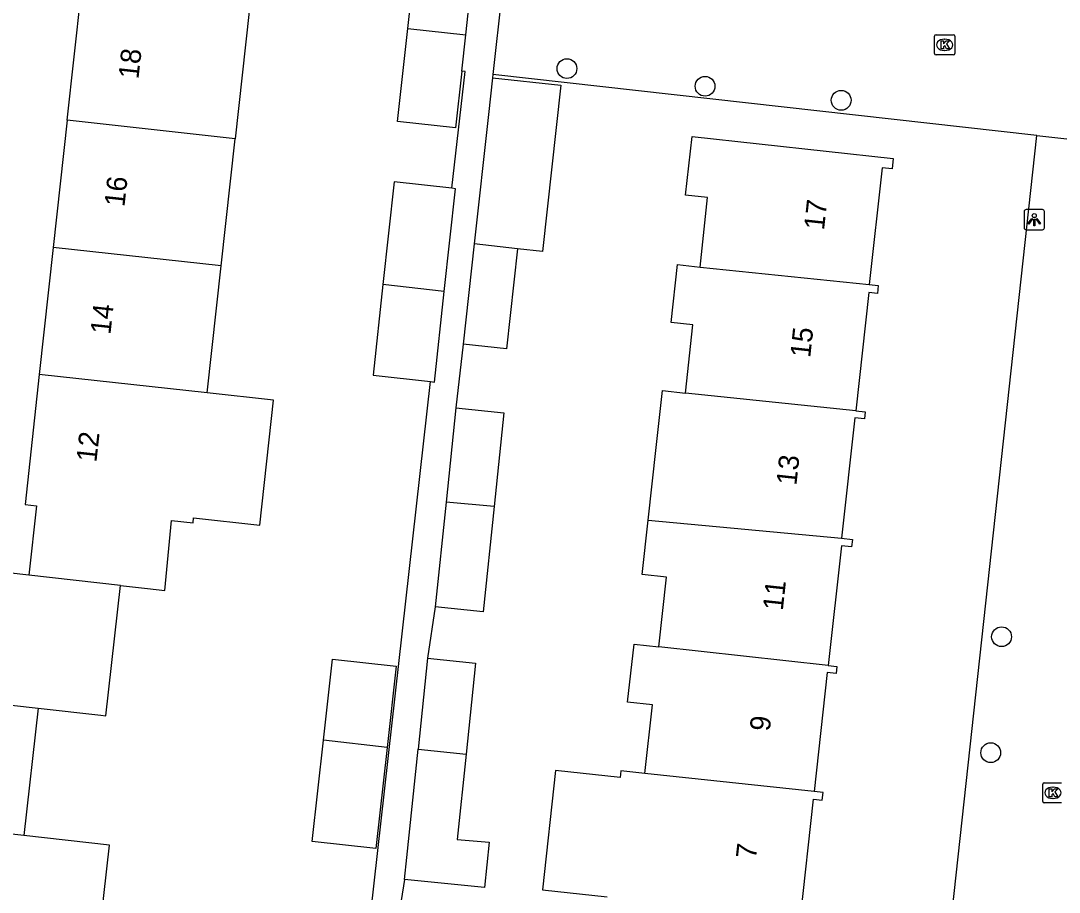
# Model space of a CAD drawing. Extents: x 162082 to 163393, y 388091 to 388632.
# Drawn here: x 162829.3 to 162880.7, y 388375.8 to 388418.8 of the extents above; entities that cross this region are included whole.
import ezdxf

# ---------------------------------------------------------------- set-up
doc = ezdxf.new("R2010")
doc.units = 0
for name, color, linetype in [('IMGEO_Boom', 7, 'Continuous'), ('IMGEO_Kolk', 7, 'Continuous'), ('IMGEO_Lichtpunt', 7, 'Continuous'), ('IMGEO_Pand', 7, 'Continuous'), ('IMGEO_Pand_nummerreeks', 7, 'Continuous'), ('IMGEO_Rijbaan_lokaal_open', 7, 'Continuous'), ('IMGEO_Voetpad_open', 7, 'Continuous')]:
    doc.layers.add(name, color=color, linetype=linetype)

msp = doc.modelspace()

# ---------------------------------------------------------------- linework, layer by layer
at = {"layer": 'IMGEO_Boom'}
for centre in [(162856.338, 388416.477), (162863.166, 388415.604), (162869.893, 388414.909), (162877.819, 388388.4), (162877.283, 388382.671)]:
    msp.add_circle(centre, 0.489, dxfattribs=at)
at = {"layer": 'IMGEO_Kolk'}
for p, q in [((162874.506, 388417.224), (162874.506, 388418.076)), ((162874.581, 388418.15), (162875.433, 388418.15)), ((162874.994, 388417.93), (162875.019, 388417.93)), ((162875.507, 388418.076), (162875.507, 388417.224)), ((162875.017, 388417.37), (162874.992, 388417.37)), ((162875.433, 388417.15), (162874.581, 388417.15)), ((162879.857, 388380.262), (162879.857, 388381.114)), ((162879.932, 388381.188), (162880.784, 388381.188)), ((162880.345, 388380.968), (162880.37, 388380.968)), ((162880.368, 388380.408), (162880.343, 388380.408)), ((162880.784, 388380.188), (162879.932, 388380.188))]:
    msp.add_line(p, q, dxfattribs=at)
for points in [[(162874.506, 388417.224), (162874.506, 388418.076)], [(162874.581, 388418.15), (162875.433, 388418.15)], [(162874.827, 388417.85), (162874.95, 388417.85), (162874.95, 388417.699), (162875.08, 388417.85), (162875.244, 388417.85), (162875.098, 388417.699), (162875.251, 388417.45), (162875.099, 388417.45), (162875.014, 388417.614), (162874.95, 388417.547), (162874.95, 388417.45), (162874.827, 388417.45), (162874.827, 388417.85)], [(162875.507, 388418.076), (162875.507, 388417.224)], [(162875.433, 388417.15), (162874.581, 388417.15)], [(162879.857, 388380.262), (162879.857, 388381.114)], [(162879.932, 388381.188), (162880.784, 388381.188)], [(162880.178, 388380.888), (162880.301, 388380.888), (162880.301, 388380.737), (162880.431, 388380.888), (162880.595, 388380.888), (162880.449, 388380.737), (162880.602, 388380.488), (162880.45, 388380.488), (162880.365, 388380.652), (162880.301, 388380.585), (162880.301, 388380.488), (162880.178, 388380.488), (162880.178, 388380.888)], [(162880.784, 388380.188), (162879.932, 388380.188)]]:
    msp.add_lwpolyline(points, dxfattribs=at)
for centre, start, end in [((162874.583, 388418.074), 91.552, 178.448), ((162874.583, 388418.074), 91.552, 178.448), ((162875.431, 388418.074), 1.552, 88.448), ((162875.431, 388418.074), 1.552, 88.448), ((162874.583, 388417.226), 181.552, 268.448), ((162874.583, 388417.226), 181.552, 268.448), ((162875.431, 388417.226), 271.552, 358.448), ((162875.431, 388417.226), 271.552, 358.448), ((162879.934, 388381.112), 91.552, 178.448), ((162879.934, 388381.112), 91.552, 178.448), ((162879.934, 388380.264), 181.552, 268.448), ((162879.934, 388380.264), 181.552, 268.448)]:
    msp.add_arc(centre, 0.0765, start, end, dxfattribs=at)
for centre, major_axis, ratio, start_param, end_param in [((162874.993, 388417.65), (-0.387, 0.002), 0.722429, 4.712389, 7.853982), ((162875.018, 388417.65), (-0.39, 0.002), 0.717154, 1.570796, 4.712389), ((162880.344, 388380.688), (-0.387, 0.002), 0.722429, 4.712389, 7.853982), ((162880.369, 388380.688), (-0.39, 0.002), 0.717154, 1.570796, 4.712389)]:
    msp.add_ellipse(centre, major_axis=major_axis, ratio=ratio, start_param=start_param, end_param=end_param, dxfattribs=at)
at = {"layer": 'IMGEO_Lichtpunt'}
for p, q in [((162878.937, 388409.413), (162878.937, 388408.606)), ((162878.937, 388409.413), (162878.937, 388408.606)), ((162879.839, 388409.508), (162879.031, 388409.508)), ((162879.839, 388409.508), (162879.031, 388409.508)), ((162879.933, 388408.606), (162879.933, 388409.413)), ((162879.933, 388408.606), (162879.933, 388409.413)), ((162879.031, 388408.512), (162879.839, 388408.512)), ((162879.031, 388408.512), (162879.839, 388408.512))]:
    msp.add_line(p, q, dxfattribs=at)
for points in [[(162879.311, 388409.077), (162879.35, 388409.049), (162879.162, 388408.787), (162879.124, 388408.814), (162879.311, 388409.077)], [(162879.523, 388409.049), (162879.561, 388409.076), (162879.748, 388408.814), (162879.709, 388408.786), (162879.523, 388409.049)], [(162879.413, 388409.029), (162879.46, 388409.029), (162879.46, 388408.707), (162879.413, 388408.707), (162879.413, 388409.029)]]:
    msp.add_lwpolyline(points, dxfattribs=at)
msp.add_circle((162879.436, 388409.211), 0.0994, dxfattribs=at)
for centre, start, end in [((162879.031, 388409.413), 90, 180), ((162879.031, 388409.413), 90, 180), ((162879.839, 388409.413), 0, 90), ((162879.839, 388409.413), 0, 90), ((162879.031, 388408.606), 180, 270), ((162879.031, 388408.606), 180, 270), ((162879.839, 388408.606), 270, 0), ((162879.839, 388408.606), 270, 360)]:
    msp.add_arc(centre, 0.0946, start, end, dxfattribs=at)
at = {"layer": 'IMGEO_Pand'}
for points in [[(162848.474, 388418.465), (162848.98, 388423.071), (162851.843, 388422.757)], [(162851.337, 388418.15), (162851.843, 388422.757)], [(162831.639, 388413.922), (162832.328, 388420.203)], [(162840.631, 388419.292), (162839.941, 388413.011)], [(162851.14, 388416.356), (162850.832, 388413.546), (162847.969, 388413.86), (162848.474, 388418.465)], [(162848.474, 388418.465), (162851.337, 388418.15)], [(162851.14, 388416.356), (162851.337, 388418.15)], [(162852.658, 388416.028), (162852.457, 388414.203), (162851.756, 388407.812)], [(162852.658, 388416.028), (162856.038, 388415.658), (162855.136, 388407.436), (162853.888, 388407.575)], [(162831.639, 388413.922), (162830.95, 388407.642)], [(162839.941, 388413.011), (162831.639, 388413.922)], [(162839.252, 388406.731), (162839.941, 388413.011)], [(162862.916, 388406.672), (162863.293, 388410.099), (162862.204, 388410.219), (162862.522, 388413.118), (162872.466, 388412.026), (162872.411, 388411.524), (162871.916, 388411.579), (162871.283, 388405.811)], [(162850.658, 388410.56), (162847.802, 388410.873), (162847.247, 388405.81)], [(162850.279, 388405.461), (162850.836, 388410.54), (162850.658, 388410.56)], [(162830.95, 388407.642), (162830.261, 388401.362)], [(162839.252, 388406.731), (162830.95, 388407.642)], [(162851.756, 388407.812), (162851.212, 388402.855)], [(162853.888, 388407.575), (162853.344, 388402.621), (162851.212, 388402.855)], [(162853.888, 388407.575), (162851.756, 388407.812)], [(162838.563, 388400.451), (162839.252, 388406.731)], [(162862.197, 388400.443), (162862.567, 388403.813), (162861.494, 388403.931), (162861.809, 388406.794), (162862.916, 388406.672)], [(162862.916, 388406.672), (162871.283, 388405.811)], [(162847.247, 388405.81), (162846.754, 388401.321), (162849.588, 388401.01)], [(162850.279, 388405.461), (162847.247, 388405.81)], [(162871.283, 388405.811), (162871.726, 388405.763), (162871.682, 388405.363), (162871.263, 388405.409), (162870.62, 388399.563)], [(162849.588, 388401.01), (162849.788, 388400.988), (162850.279, 388405.461)], [(162830.261, 388401.362), (162829.556, 388394.934), (162830.121, 388394.873), (162829.744, 388391.446)], [(162838.563, 388400.451), (162830.261, 388401.362)], [(162834.278, 388390.929), (162835.606, 388390.777), (162836.468, 388390.678), (162836.793, 388394.14), (162837.858, 388394.023), (162837.885, 388394.273), (162841.161, 388393.914), (162841.839, 388400.092), (162838.563, 388400.451)], [(162860.357, 388394.162), (162860.749, 388397.758), (162861.058, 388400.568), (162862.197, 388400.443)], [(162870.62, 388399.563), (162862.197, 388400.443)], [(162850.847, 388399.718), (162850.362, 388395.056)], [(162850.847, 388399.718), (162853.223, 388399.471), (162852.741, 388394.838)], [(162870.62, 388399.563), (162871.08, 388399.512), (162871.044, 388399.176), (162870.57, 388399.214), (162869.916, 388393.265)], [(162850.362, 388395.056), (162849.823, 388389.872)], [(162852.741, 388394.838), (162852.199, 388389.625), (162849.823, 388389.872)], [(162852.741, 388394.838), (162850.362, 388395.056)], [(162860.882, 388387.905), (162861.261, 388391.346), (162860.062, 388391.478), (162860.357, 388394.162)], [(162860.357, 388394.162), (162869.916, 388393.265)], [(162869.916, 388393.265), (162870.447, 388393.207), (162870.407, 388392.843), (162869.908, 388392.898), (162869.257, 388386.973)], [(162829.744, 388391.446), (162822.577, 388392.254), (162821.851, 388385.81)], [(162834.278, 388390.929), (162829.744, 388391.446)], [(162830.212, 388384.87), (162833.296, 388384.523), (162833.544, 388384.495), (162834.278, 388390.929)], [(162860.196, 388381.649), (162860.568, 388385.035), (162859.34, 388385.17), (162859.655, 388388.04), (162860.882, 388387.905)], [(162869.257, 388386.973), (162860.882, 388387.905)], [(162844.313, 388383.285), (162844.76, 388387.292), (162847.9, 388386.941), (162847.453, 388382.932)], [(162849.446, 388387.344), (162848.978, 388382.847)], [(162849.446, 388387.344), (162851.821, 388387.097), (162851.353, 388382.593)], [(162869.257, 388386.973), (162869.678, 388386.927), (162869.641, 388386.584), (162869.204, 388386.632), (162868.559, 388380.756)], [(162821.851, 388385.81), (162830.212, 388384.87)], [(162830.212, 388384.87), (162829.503, 388378.573)], [(162847.453, 388382.932), (162846.895, 388377.932), (162843.755, 388378.283), (162844.313, 388383.285)], [(162847.453, 388382.932), (162844.313, 388383.285)], [(162848.309, 388376.412), (162848.422, 388377.497), (162848.978, 388382.847)], [(162851.353, 388382.593), (162850.915, 388378.373), (162852.497, 388378.251), (162852.263, 388376.001), (162848.309, 388376.412)], [(162848.978, 388382.847), (162851.353, 388382.593)], [(162860.196, 388381.649), (162858.999, 388381.78), (162858.963, 388381.45), (162855.772, 388381.795), (162855.134, 388375.894), (162858.321, 388375.55)], [(162868.559, 388380.756), (162860.196, 388381.649)], [(162867.882, 388374.516), (162868.526, 388380.379), (162868.956, 388380.332), (162868.998, 388380.707), (162868.559, 388380.756)], [(162829.503, 388378.573), (162821.142, 388379.514)], [(162828.794, 388372.278), (162833.018, 388371.802), (162833.727, 388378.098), (162829.503, 388378.573)]]:
    msp.add_lwpolyline(points, dxfattribs=at)
at = {"layer": 'IMGEO_Rijbaan_lokaal_open'}
for points in [[(162853.562, 388424.174), (162852.675, 388416.184)], [(162879.563, 388413.177), (162852.675, 388416.184)], [(162873.15, 388354.422), (162879.563, 388413.177)], [(162879.563, 388413.177), (162888.58, 388412.169)]]:
    msp.add_lwpolyline(points, dxfattribs=at)
at = {"layer": 'IMGEO_Voetpad_open'}
for points in [[(162850.658, 388410.56), (162851.305, 388416.338), (162851.14, 388416.356)], [(162852.675, 388416.184), (162852.658, 388416.028)], [(162851.212, 388402.855), (162850.847, 388399.718)], [(162845.249, 388362.283), (162849.588, 388401.01)], [(162849.823, 388389.872), (162849.446, 388387.344)], [(162848.309, 388376.412), (162848.03, 388374.637)]]:
    msp.add_lwpolyline(points, dxfattribs=at)

# ---------------------------------------------------------------- texts
at = {"layer": 'IMGEO_Pand_nummerreeks'}
for s, rotation, p in [('18', 83.7388, (162835.16, 388415.933)), ('16', 83.7388, (162834.467, 388409.62)), ('17', 83.8168, (162869.044, 388408.467)), ('14', 83.7388, (162833.775, 388403.311)), ('15', 83.8168, (162868.36, 388402.161)), ('12', 83.7378, (162833.082, 388396.998)), ('13', 83.8168, (162867.677, 388395.855)), ('11', 83.8168, (162867.006, 388389.663)), ('9', 83.8168, (162866.361, 388383.7)), ('7', 83.818, (162865.678, 388377.394))]:
    msp.add_text(s, height=1, rotation=rotation, dxfattribs=at).set_placement(p)

doc.saveas('drawing.dxf')
